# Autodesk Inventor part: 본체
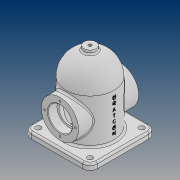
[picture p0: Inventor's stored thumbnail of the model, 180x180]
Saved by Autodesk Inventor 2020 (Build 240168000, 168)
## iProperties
Created: 2021-08
Part Number: 본체
Material: 일반
Document SubType Name: Modeling
Designer: PC312-
Density: 1 g/cm^3
Appearance: 기본값
Author: PC312-
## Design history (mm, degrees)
sketch "스케치2"
  geometry: C1 r 40 at (0, 0); 1 further point
  constraints: 1 centre point, 1 coincident
  dimensions: "d0" = 80 diameter of C1
extrude "돌출1" new body sketch "스케치2" distance "d1" = 84; taper "d2" = 0 deg
sketch "스케치3"
  geometry: L1 (40, 0)-(-40, 0); L2 (40, 84)-(-40, 84) reference; L3 (0, 124)-(0, 84); A1 r 40 centre (0, 84) between (0, 124) and (-40, 84); 2 further points
  constraints: 2 end point, 2 point on circle, 1 centre point, 1 midpoint, 1 point on line, 1 vertical
  dimensions: "d4" = 40 radius of A1
revolve "회전1" sketch "스케치3" stored, may be unused: angle "d5" = 360 deg
feature "쉘1" dims "d7" = 8
sketch "스케치5"
  geometry: L1 (-55, 55)-(55, 55); L2 (55, 55)-(55, -55); L3 (55, -55)-(-55, -55); L4 (-55, -55)-(-55, 55); L5 (-55, 55)-(55, -55); L6 (55, 55)-(-55, -55); C1 r 32 at (0, 0) reference; 1 further point
  constraints: 12 end point, 2 midpoint, 2 parallel, 1 horizontal, 1 perpendicular
  dimensions: "d8" = 110 distance of L2.end L3.end; "d9" = 110 distance of L1.end L2.end
extrude "돌출2" cut sketch "스케치5" distance "d10" = 10; taper "d11" = 0 deg
extrude "돌출3" join sketch "스케치5" distance "d12" = 10; taper "d13" = 0 deg
node "작업 평면1"
sketch "스케치6"
  geometry: C1 r 10 at (0, 0); 1 further point
  constraints: 1 centre point, 1 coincident
  dimensions: "d15" = 20 diameter of C1
extrude "돌출4" join sketch "스케치6" stored distance "d16" = 10; taper "d17" = 0 deg
sketch "스케치7"
  geometry: C1 r 10 at (0, 0) reference; 2 further points
  constraints: 1 coincident
hole "구멍1" sketch "스케치7" at (0, 0) diameter "d18" = 5.1881; stored, may be unused: countersink angle "d22" = 90 deg, drill point angle "d24" = 0 deg; dims "d19" = 12, "d20" = 4, "d21" = 2, "d23" = 16
node "작업 평면2"
sketch "스케치8"
  geometry: L1 (55, 0)-(-55, 0) reference; C1 r 31 at (0, 48); 2 further points
  constraints: 1 centre point, 1 midpoint, 1 vertical alignment
  dimensions: "d26" = 62 diameter of C1; "d27" = 48 distance from line of L1 C1.centre
extrude "돌출5" join sketch "스케치8" stored distance "d28" = 10; taper "d29" = 0 deg
sketch "스케치9"
  geometry: C1 r 20 at (0, 0); C2 r 31 at (0, 0) reference; 1 further point
  constraints: 1 centre point, 1 concentric
  dimensions: "d30" = 40 diameter of C1
extrude "돌출6" cut sketch "스케치9" distance "d31" = 15; taper "d32" = 0 deg
sketch "스케치10" dims "d33" = 51
  geometry: C1 r 31 at (0, 0) reference; 3 further points
  constraints: 2 vertical alignment, 3 other
hole "구멍2" sketch "스케치10" at (0, 25.5) diameter "d34" = 3.242; stored, may be unused: countersink angle "d38" = 90 deg, drill point angle "d40" = 118 deg; dims "d35" = 8, "d36" = 4, "d37" = 2, "d39" = 10
sketch "스케치11"
  geometry: C1 r 16.5 at (0, 0); C2 r 20 at (0, 0) reference; 1 further point
  constraints: 1 centre point, 1 concentric
  dimensions: "d44" = 33 diameter of C1
extrude "돌출7" cut sketch "스케치11" extent not by distance; stored distance "d45" = 15; taper "d46" = 0 deg
fillet "모깎기1" dims "d47" = 12
sketch "스케치13"
  geometry: C1 r 4.5 at (-43, -43); C2 r 4.5 at (-43, 43); C3 r 4.5 at (43, -43); C4 r 4.5 at (43, 43); A1 r 12 centre (-43, -43) between (-55, -43) and (-43, -55) reference; A2 r 12 centre (-43, 43) between (-43, 55) and (-55, 43) reference; A3 r 12 centre (43, -43) between (43, -55) and (55, -43) reference; A4 r 12 centre (43, 43) between (55, 43) and (43, 55) reference; 1 further point
  constraints: 4 centre point, 4 concentric
  dimensions: "d48" = 9 diameter of C1; "d49" = 9 diameter of C2; "d50" = 9 diameter of C3; "d51" = 9 diameter of C4
extrude "돌출8" cut sketch "스케치13" distance "d52" = 15; taper "d53" = 0 deg
chamfer "모따기1" distance "d54" = 1; stored, may be unused: second distance "d55" = 2, angle "d56" = 45 deg
fillet "모깎기2" dims "d57" = 3
fillet "모깎기3" dims "d58" = 3
fillet "모깎기4" dims "d59" = 3
node "작업 평면3"
sketch "스케치14"
  geometry: L1 (0, -43)-(0, 43) reference; 4 further points
  constraints: 2 midpoint, 1 horizontal alignment, 1 other
  dimensions: "d62" = 48 distance from line of L1 point (48, 0)
feature "엠보싱1" sketch "스케치14" dims "d1" = 84, "d63" = 0.5, "d64" = 0
fillet "모깎기5" dims "d65" = 3
node "솔리드1"
mirror "미러1"
pattern_circular "원형 패턴1" dims angle "d42" = 360 deg
mirror "미러2"
feature "A9D066F2-1C7D-4E18-AEED-F7BC21143FA4" dims "d34" = 3.242, "d35" = 8, "d36" = 4, "d37" = 2, "d38" = 90 deg, "d39" = 10, "d40" = 118 deg
other parameters: "d14" = -129, "d60" = 52.25
